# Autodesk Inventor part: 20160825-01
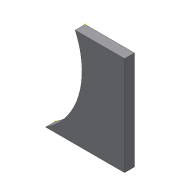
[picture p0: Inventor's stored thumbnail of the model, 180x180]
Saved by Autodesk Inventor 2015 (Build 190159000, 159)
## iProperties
Created: 2016-08
Part Number: 20160825-01
Material: Všeobecné
Document SubType Name: Modeling
Designer: navara
Density: 1 g/cm^3
Appearance: Výchozí
Beppe: 20160825-01.ipt
Author: navara
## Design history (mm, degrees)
sketch "Náčrt1"
  geometry: L1 (0, 0)-(0, -100); L2 (0, -100)-(80, -100); L3 (0, 0)-(50, 0); A1 r 80 centre (123.065, -32.58) between (50, 0) and (80, -100); 1 further point
  constraints: 6 end point, 2 point on circle, 1 centre point, 1 coincident, 1 horizontal, 1 perpendicular, 1 vertical
  dimensions: "d0" = 100 distance of L1.start L1.end; "d1" = 80 distance of L1.end L2.end; "d2" = 50 distance of L1.start L3.end; "d3" = 80 radius of A1
extrude "Vysunutí1" new body sketch "Náčrt1" distance "d4" = 10; taper "d5" = 0 deg
node "Pracovní bod1"
pattern_linear "Obdélníkové pole1"
node "Těleso1"
node "Pracovní bod2"
node "Pracovní bod3"
node "Pracovní bod4"
node "Pracovní bod5"
node "Pracovní bod6"
node "Pracovní bod7"
